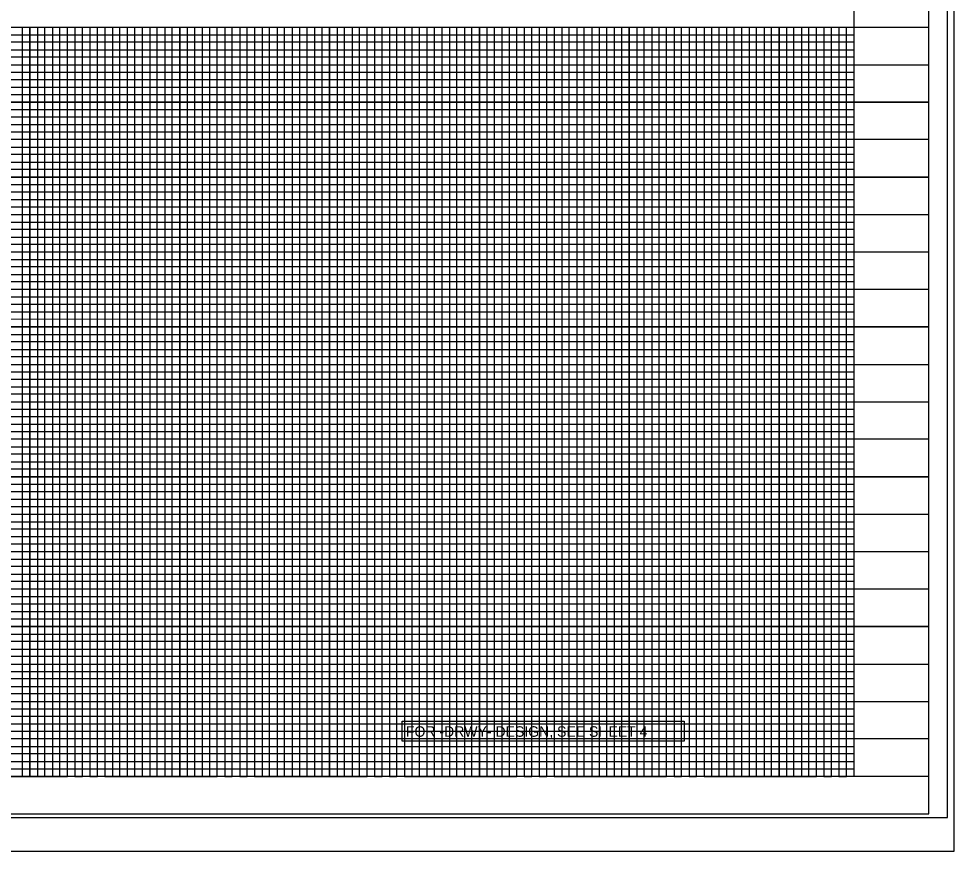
# Model space of a CAD drawing. Extents: x 10070 to 15319, y 8517 to 10343.
# Drawn here: x 14267 to 14892, y 8517 to 9072 of the extents above; entities that cross this region are included whole.
import ezdxf

# ---------------------------------------------------------------- set-up
doc = ezdxf.new("R2010")
doc.units = 0
for name, color, linetype in [('Prop Grid Mask', 7, 'Continuous'), ('Prop VPI Label', 7, 'Continuous'), ('Scratch_Level_3', 7, 'Continuous'), ('Sheet Cutting Line CELL', 7, 'Continuous'), ('Sheet DOT Grid CELL', 7, 'Continuous'), ('Sheet Layout Profile Border Port 2', 7, 'Continuous'), ('Sheet Plot Border Inside CELL', 7, 'Continuous'), ('Sheet Plot Border Outside CELL', 7, 'Continuous'), ('Sheet Profile CELL', 7, 'Continuous'), ('Sheet Profile Grid Major CELL', 7, 'Continuous'), ('Sheet Profile Grid Middle CELL', 7, 'Continuous'), ('Sheet Profile Grid Minor CELL', 7, 'Continuous')]:
    doc.layers.add(name, color=color, linetype=linetype)

msp = doc.modelspace()

# ---------------------------------------------------------------- linework, layer by layer
at = {"layer": 'Prop Grid Mask'}
msp.add_lwpolyline([(14523.43, 8590.13), (14523.43, 8603.5), (14711.74, 8603.5), (14711.74, 8590.13)], close=True, dxfattribs=at)
at = {"layer": 'Scratch_Level_3'}
msp.add_lwpolyline([(13374.94, 9591.73), (14824.91, 9591.73), (14824.91, 8566.73), (13374.94, 8566.73)], close=True, dxfattribs=at)
at = {"layer": 'Sheet Cutting Line CELL'}
msp.add_line((13207.94, 8516.73), (14891.94, 8516.73), dxfattribs=at)
at = {"layer": 'Sheet DOT Grid CELL'}
for p, q in [((13374.94, 9066.73), (14874.83, 9066.73)), ((14274.94, 9066.73), (14274.94, 8566.73)), ((14324.94, 9066.73), (14324.94, 8566.73)), ((14374.94, 9066.73), (14374.94, 8566.73)), ((14424.94, 9066.73), (14424.94, 8566.73)), ((14474.94, 9066.73), (14474.94, 8566.73)), ((14524.94, 9066.73), (14524.94, 8566.73)), ((14574.94, 9066.73), (14574.94, 8566.73)), ((14624.94, 9066.73), (14624.94, 8566.73)), ((14674.94, 9066.73), (14674.94, 8566.73)), ((14724.94, 9066.73), (14724.94, 8566.73)), ((14774.94, 9066.73), (14774.94, 8566.73)), ((14824.94, 9066.73), (14824.94, 8566.73)), ((13374.94, 9016.73), (14874.83, 9016.73)), ((13374.94, 8966.73), (14874.83, 8966.73)), ((13374.94, 8916.73), (14874.83, 8916.73)), ((13374.94, 8866.73), (14874.83, 8866.73)), ((13374.94, 8816.73), (14874.83, 8816.73)), ((13374.94, 8766.73), (14874.83, 8766.73)), ((13374.94, 8716.73), (14874.83, 8716.73)), ((13374.94, 8666.73), (14874.83, 8666.73)), ((13374.94, 8616.73), (14874.83, 8616.73))]:
    msp.add_line(p, q, dxfattribs=at)
at = {"layer": 'Sheet Layout Profile Border Port 2'}
msp.add_lwpolyline([(13424.94, 9066.73), (14824.94, 9066.73), (14824.94, 8566.73), (13424.94, 8566.73)], close=True, dxfattribs=at)
at = {"layer": 'Sheet Plot Border Inside CELL'}
msp.add_lwpolyline([(13220.94, 8539.18), (14887.44, 8539.18), (14887.44, 9594.28), (13220.94, 9594.28)], close=True, dxfattribs=at)
at = {"layer": 'Sheet Plot Border Outside CELL'}
msp.add_lwpolyline([(13207.94, 8516.73), (14891.94, 8516.73), (14891.94, 9616.73), (13207.94, 9616.73)], close=True, dxfattribs=at)
at = {"layer": 'Sheet Profile CELL'}
for p, q in [((13374.94, 9066.73), (14874.94, 9066.73)), ((14874.94, 8566.73), (13374.94, 8566.73)), ((13374.94, 8541.73), (14874.94, 8541.73))]:
    msp.add_line(p, q, dxfattribs=at)
msp.add_lwpolyline([(14874.94, 9591.73), (13374.94, 9591.73), (13374.94, 8541.73), (14874.94, 8541.73)], close=True, dxfattribs=at)
at = {"layer": 'Sheet Profile Grid Major CELL'}
for p, q in [((14274.94, 9066.73), (14324.94, 9066.73)), ((14374.94, 9066.73), (14424.94, 9066.73)), ((14474.94, 9066.73), (14524.94, 9066.73)), ((14574.94, 9066.73), (14624.94, 9066.73)), ((14674.94, 9066.73), (14724.94, 9066.73)), ((14774.94, 9066.73), (14824.94, 9066.73)), ((14774.94, 8566.73), (14774.94, 8566.73))]:
    msp.add_line(p, q, dxfattribs=at)
for points in [[(14224.94, 8566.73), (14274.94, 8566.73), (14274.94, 9066.73), (14324.94, 9066.73), (14324.94, 8566.73), (14374.94, 8566.73), (14374.94, 9066.73), (14424.94, 9066.73), (14424.94, 8566.73), (14474.94, 8566.73), (14474.94, 9066.73), (14524.94, 9066.73), (14524.94, 8566.73), (14574.94, 8566.73), (14574.94, 9066.73), (14624.94, 9066.73), (14624.94, 8566.73), (14674.94, 8566.73), (14674.94, 9066.73), (14724.94, 9066.73), (14724.94, 8566.73), (14774.94, 8566.73), (14774.94, 8566.73), (14774.94, 9066.73), (14824.94, 9066.73), (14824.94, 8566.73)], [(14874.94, 9016.73), (13374.94, 9016.73)], [(14874.94, 8966.73), (13374.94, 8966.73), (13374.94, 8916.73), (14874.94, 8916.73)], [(14874.94, 8866.73), (13374.94, 8866.73), (13374.94, 8816.73), (14874.94, 8816.73)], [(14874.94, 8766.73), (13374.94, 8766.73), (13374.94, 8716.73), (14874.94, 8716.73)], [(14874.94, 8666.73), (13374.94, 8666.73), (13374.94, 8666.73), (13374.94, 8616.73), (14874.94, 8616.73)], [(14874.94, 8566.73), (13374.94, 8566.73)]]:
    msp.add_lwpolyline(points, dxfattribs=at)
at = {"layer": 'Sheet Profile Grid Middle CELL'}
for points in [[(14249.94, 8566.73), (14299.94, 8566.73), (14299.94, 9066.73), (14349.94, 9066.73), (14349.94, 8566.73), (14399.94, 8566.73), (14399.94, 9066.73), (14449.94, 9066.73), (14449.94, 8566.73), (14499.94, 8566.73), (14499.94, 9066.73), (14549.94, 9066.73), (14549.94, 8566.73), (14599.94, 8566.73), (14599.94, 9066.73), (14649.94, 9066.73), (14649.94, 8566.73), (14699.94, 8566.73), (14699.94, 9066.73), (14749.94, 9066.73), (14749.94, 8566.73), (14799.94, 8566.73), (14799.94, 9066.73)], [(13374.94, 9041.73), (14874.94, 9041.73)], [(14874.94, 8991.73), (13374.94, 8991.73), (13374.94, 8941.73), (14874.94, 8941.73)], [(14874.94, 8891.73), (13374.94, 8891.73), (13374.94, 8841.73), (14874.94, 8841.73)], [(14874.94, 8791.73), (13374.94, 8791.73), (13374.94, 8741.73), (14874.94, 8741.73)], [(14874.94, 8691.73), (13374.94, 8691.73), (13374.94, 8641.73), (14874.94, 8641.73)], [(14874.94, 8591.73), (13374.94, 8591.73)]]:
    msp.add_lwpolyline(points, dxfattribs=at)
at = {"layer": 'Sheet Profile Grid Minor CELL'}
for p, q in [((13424.94, 9061.73), (14824.94, 9061.73)), ((14824.94, 9056.73), (13424.94, 9056.73)), ((13424.94, 9051.73), (14824.94, 9051.73)), ((14824.94, 9046.73), (13424.94, 9046.73)), ((13424.94, 9036.73), (14824.94, 9036.73)), ((14824.94, 9031.73), (13424.94, 9031.73)), ((13424.94, 9026.73), (14824.94, 9026.73)), ((14824.94, 9021.73), (13424.94, 9021.73)), ((13424.94, 9011.73), (14824.94, 9011.73)), ((14824.94, 9006.73), (13424.94, 9006.73)), ((13424.94, 9001.73), (14824.94, 9001.73)), ((14824.94, 8996.73), (13424.94, 8996.73)), ((13424.94, 8986.73), (14824.94, 8986.73)), ((14824.94, 8981.73), (13424.94, 8981.73)), ((13424.94, 8976.73), (14824.94, 8976.73)), ((14824.94, 8971.73), (13424.94, 8971.73)), ((13424.94, 8961.73), (14824.94, 8961.73)), ((14824.94, 8956.73), (13424.94, 8956.73)), ((13424.94, 8951.73), (14824.94, 8951.73)), ((14824.94, 8946.73), (13424.94, 8946.73)), ((13424.94, 8936.73), (14824.94, 8936.73)), ((14824.94, 8931.73), (13424.94, 8931.73)), ((13424.94, 8926.73), (14824.94, 8926.73)), ((14824.94, 8921.73), (13424.94, 8921.73)), ((13424.94, 8911.73), (14824.94, 8911.73)), ((14824.94, 8906.73), (13424.94, 8906.73)), ((13424.94, 8901.73), (14824.94, 8901.73)), ((14824.94, 8896.73), (13424.94, 8896.73)), ((13424.94, 8886.73), (14824.94, 8886.73)), ((14824.94, 8881.73), (13424.94, 8881.73)), ((13424.94, 8876.73), (14824.94, 8876.73)), ((14824.94, 8871.73), (13424.94, 8871.88)), ((13424.94, 8861.73), (14824.94, 8861.73)), ((14824.94, 8856.73), (13424.94, 8856.73)), ((13424.94, 8851.73), (14824.94, 8851.73)), ((14824.94, 8846.73), (13424.94, 8846.73)), ((13424.94, 8836.73), (14824.94, 8836.73)), ((14824.94, 8831.73), (13424.94, 8831.73)), ((13424.94, 8826.73), (14824.94, 8826.73)), ((14824.94, 8821.73), (13424.94, 8821.73)), ((13424.94, 8811.73), (14824.94, 8811.73)), ((14824.94, 8806.73), (13424.94, 8806.73)), ((13424.94, 8801.73), (14824.94, 8801.73)), ((14824.94, 8796.73), (13424.94, 8796.73)), ((13424.94, 8786.73), (14824.94, 8786.73)), ((14824.94, 8781.73), (13424.94, 8781.73)), ((13424.94, 8776.73), (14824.94, 8776.73)), ((14824.94, 8771.73), (13424.94, 8771.73)), ((13424.94, 8761.73), (14824.94, 8761.73)), ((14824.94, 8756.73), (13424.94, 8756.73)), ((13424.94, 8751.73), (14824.94, 8751.73)), ((14824.94, 8746.73), (13424.94, 8746.73)), ((13424.94, 8736.73), (14824.94, 8736.73)), ((14824.94, 8731.73), (13424.94, 8731.73)), ((13424.94, 8726.73), (14824.94, 8726.73)), ((14824.94, 8721.73), (13424.94, 8721.73)), ((13424.94, 8711.73), (14824.94, 8711.73)), ((14824.94, 8706.73), (13424.94, 8706.73)), ((13424.94, 8701.73), (14824.94, 8701.73)), ((14824.94, 8696.73), (13424.94, 8696.73)), ((13424.94, 8686.73), (14824.94, 8686.73)), ((14824.94, 8681.73), (13424.94, 8681.73)), ((13424.94, 8676.73), (14824.94, 8676.73)), ((14824.94, 8671.73), (13424.94, 8671.73)), ((13424.94, 8661.73), (14824.94, 8661.73)), ((14824.94, 8656.73), (13424.94, 8656.73)), ((13424.94, 8651.73), (14824.94, 8651.73)), ((14824.94, 8646.73), (13424.94, 8646.73)), ((13424.94, 8636.73), (14824.94, 8636.73)), ((14824.94, 8631.73), (13424.94, 8631.73)), ((13424.94, 8626.73), (14824.94, 8626.73)), ((14824.94, 8621.73), (13424.94, 8621.73)), ((13424.94, 8611.73), (14824.94, 8611.73)), ((14824.94, 8606.73), (13424.94, 8606.73)), ((13424.94, 8601.73), (14824.94, 8601.73)), ((14824.94, 8596.73), (13424.94, 8596.73)), ((13424.94, 8586.73), (14824.94, 8586.73)), ((14824.94, 8581.73), (13424.94, 8581.73)), ((13424.94, 8576.73), (14824.94, 8576.73)), ((13424.94, 8571.73), (14824.94, 8571.73)), ((14824.94, 8571.73), (14824.94, 8571.73))]:
    msp.add_line(p, q, dxfattribs=at)
for points in [[(14264.94, 8566.73), (14269.94, 8566.73), (14269.94, 9066.73), (14279.94, 9066.73), (14279.94, 8566.73), (14284.94, 8566.73), (14284.94, 9066.73), (14289.94, 9066.73), (14289.94, 8566.73), (14294.94, 8566.73), (14294.94, 9066.73), (14304.94, 9066.73), (14304.94, 8566.73), (14309.94, 8566.73), (14309.94, 9066.73), (14314.94, 9066.73), (14314.94, 8566.73), (14319.94, 8566.73), (14319.94, 9066.73), (14329.94, 9066.73), (14329.94, 8566.73), (14334.94, 8566.73), (14334.94, 9066.73), (14339.94, 9066.73), (14339.94, 8566.73), (14344.94, 8566.73), (14344.94, 9066.73), (14354.94, 9066.73), (14354.94, 8566.73), (14359.94, 8566.73), (14359.94, 9066.73), (14364.94, 9066.73), (14364.94, 8566.73), (14369.94, 8566.73), (14369.94, 9066.73), (14379.94, 9066.73), (14379.94, 8566.73), (14384.94, 8566.73), (14384.94, 9066.73), (14389.94, 9066.73), (14389.94, 8566.73), (14394.94, 8566.73), (14394.94, 9066.73), (14404.94, 9066.73), (14404.94, 8566.73), (14409.94, 8566.73), (14409.94, 9066.73), (14414.94, 9066.73), (14414.94, 8566.73), (14419.94, 8566.73), (14419.94, 9066.73), (14429.94, 9066.73), (14429.94, 8566.73), (14434.94, 8566.73), (14434.94, 9066.73), (14439.94, 9066.73), (14439.94, 8566.73), (14444.94, 8566.73), (14444.94, 9066.73), (14454.94, 9066.73), (14454.94, 8566.73), (14459.94, 8566.73), (14459.94, 9066.73), (14464.94, 9066.73), (14464.94, 8566.73), (14469.94, 8566.73), (14469.94, 9066.73), (14479.94, 9066.73), (14479.94, 8566.73), (14484.94, 8566.73), (14484.94, 9066.73), (14489.94, 9066.73), (14489.94, 8566.73), (14494.94, 8566.73), (14494.94, 9066.73), (14504.94, 9066.73), (14504.94, 8566.73), (14509.94, 8566.73), (14509.94, 9066.73), (14514.94, 9066.73), (14514.94, 8566.73), (14519.94, 8566.73), (14519.94, 9066.73), (14529.94, 9066.73), (14529.94, 8566.73), (14534.94, 8566.73), (14534.94, 9066.73), (14539.94, 9066.73), (14539.94, 8566.73), (14544.94, 8566.73), (14544.94, 9066.73), (14554.94, 9066.73), (14554.94, 8566.73), (14559.94, 8566.73), (14559.94, 9066.73), (14564.94, 9066.73), (14564.94, 8566.73)], [(14564.94, 8566.73), (14569.94, 8566.73), (14569.94, 9066.73), (14579.94, 9066.73), (14579.94, 8566.73), (14584.94, 8566.73), (14584.94, 9066.73), (14589.94, 9066.73), (14589.94, 8566.73), (14594.94, 8566.73), (14594.94, 9066.73), (14604.94, 9066.73), (14604.94, 8566.73), (14609.94, 8566.73), (14609.94, 9066.73), (14614.94, 9066.73), (14614.94, 8566.73), (14619.94, 8566.73), (14619.94, 9066.73), (14629.94, 9066.73), (14629.94, 8566.73), (14634.94, 8566.73), (14634.94, 9066.73), (14639.94, 9066.73), (14639.94, 8566.73), (14644.94, 8566.73), (14644.94, 9066.73), (14654.94, 9066.73), (14654.94, 8566.73), (14659.94, 8566.73), (14659.94, 9066.73), (14664.94, 9066.73), (14664.94, 8566.73), (14669.94, 8566.73), (14669.94, 9066.73), (14679.94, 9066.73), (14679.94, 8566.73), (14684.94, 8566.73), (14684.94, 9066.73), (14689.94, 9066.73), (14689.94, 8566.73), (14694.94, 8566.73), (14694.94, 9066.73), (14704.94, 9066.73), (14704.94, 8566.73), (14709.94, 8566.73), (14709.94, 9066.73), (14714.94, 9066.73), (14714.94, 8566.73), (14719.94, 8566.73), (14719.94, 9066.73), (14729.94, 9066.73), (14729.94, 8566.73), (14734.94, 8566.73), (14734.94, 9066.73), (14739.94, 9066.73), (14739.94, 8566.73), (14744.94, 8566.73), (14744.94, 9066.73), (14754.94, 9066.73), (14754.94, 8566.73), (14759.94, 8566.73), (14759.94, 9066.73), (14764.94, 9066.73), (14764.94, 8566.73), (14769.94, 8566.73), (14769.94, 9066.73), (14779.94, 9066.73), (14779.94, 8566.73), (14784.94, 8566.73), (14784.94, 9066.73), (14789.94, 9066.73), (14789.94, 8566.73), (14794.94, 8566.73), (14794.94, 9066.73), (14804.94, 9066.73), (14804.94, 8566.73), (14809.94, 8566.73), (14809.94, 9066.73), (14814.94, 9066.73), (14814.94, 8566.73), (14819.94, 8566.73), (14819.94, 9066.73), (14824.94, 9066.73)]]:
    msp.add_lwpolyline(points, dxfattribs=at)

# ---------------------------------------------------------------- texts
at = {"layer": 'Prop VPI Label'}
msp.add_text('FOR -DRWY- DESIGN, SEE SHEET 4', height=7, dxfattribs=at).set_placement((14525.89, 8593.17))

doc.saveas('drawing.dxf')
